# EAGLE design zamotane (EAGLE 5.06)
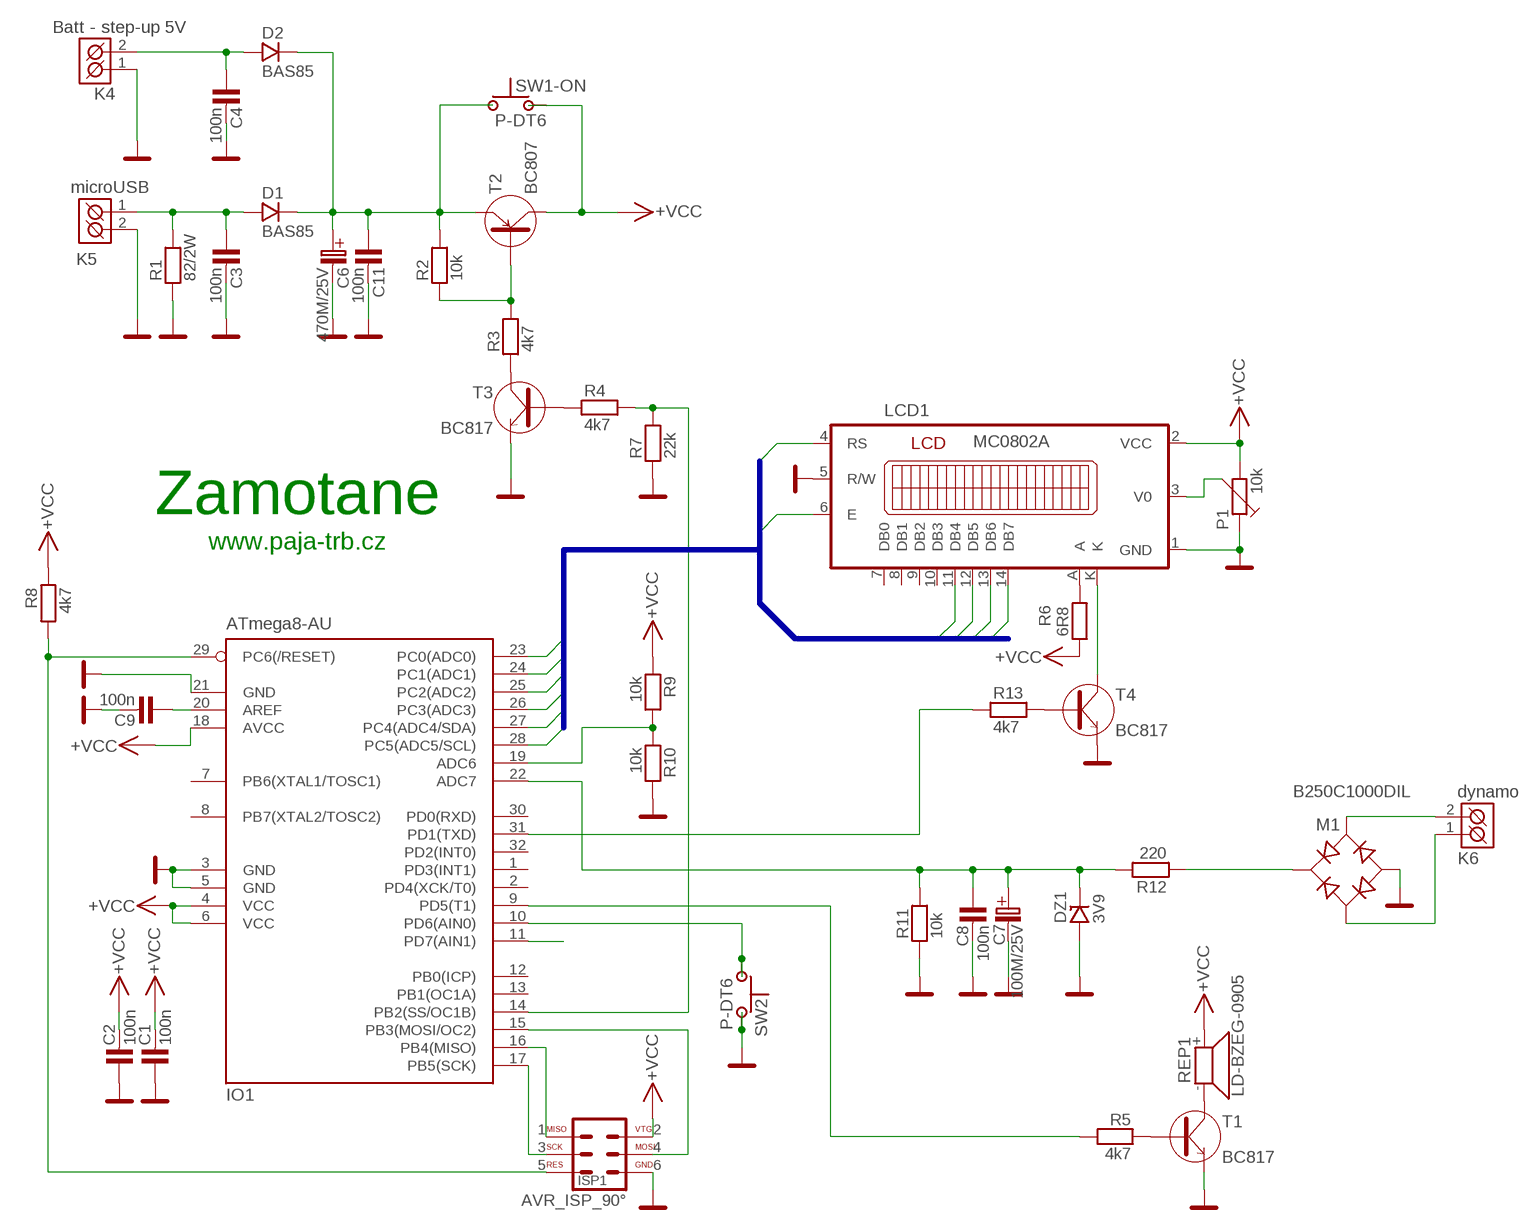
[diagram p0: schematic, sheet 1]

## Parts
C1  100n  C-KER_0805  [0805]
C2  100n  C-KER_0805  [0805]
C3  100n  C-KERAMIK_SMD_1206  [1206]
C4  100n  C-KERAMIK_SMD_1206  [1206]
C6  470M/25V  C-EL_5  [C-EL_5]
C7  100M/25V  [C_EL_2,5]
C8  100n  C-KERAMIK_SMD_1206  [1206]
C9  100n  C-KER_0805  [0805]
C11  100n  C-KERAMIK_SMD_1206  [1206]
D1  BAS85  1N4148.  [SOD-80]
D2  BAS85  1N4148.  [SOD-80]
DZ1  3V9  D-BZV55C_SMD_0,5W-ZENER  [SOD-80]
IO1  ATmega8-AU  MEGA8-AI  [TQFP32-08]
ISP1  AVR_ISP_90°  [MLW06A]
K4  Batt - step-up 5V  ARK500/2  [ARK500/2]
K5  microUSB  ARK500/2  [ARK500/2]
K6  dynamo  ARK500/2  [ARK500/2]
LCD1  MC0802A  [MC0802A-SYL]
M1  B250C1000DIL  D-B250C1000DIL_MUSTEK  [DM_DB1]
P1  10k  TRIMRPT6H  [PT6H]
R1  82/2W  R__2W  [R-_2W]
R2  10k  R_1206  [1206]
R3  4k7  R_1206  [1206]
R4  4k7  R_1206  [1206]
R5  4k7  R_1206  [1206]
R6  6R8  R_1206  [1206]
R7  22k  R_1206  [1206]
R8  4k7  R_1206  [1206]
R9  10k  R_0805  [0805]
R10  10k  R_0805  [0805]
R11  10k  R_1206  [1206]
R12  220  R_1206  [1206]
R13  4k7  R_1206  [1206]
REP1  LD-BZEG-0905  SIR_0905  [LD-BZEG-0905]
SW1-ON  P-DT6  [P-DT6]
SW2  P-DT6  [P-DT6]
T1  BC817  [SOT-23]
T2  BC807  [SOT-23]
T3  BC817  [SOT-23]
T4  BC817  BC846  [SOT-23]

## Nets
+5V: C6.C+(C_EL+) C11.1 D1.K D2.K R2.2 SW1-ON.1 SW1-ON.1A T2.2(E)
ADC7: C7.C+(C_EL+) C8.1 DZ1.K IO1.22(ADC7) R11.2 R12.2
DB4: IO1.25(PC2(ADC2)) LCD1.11(DB4)
DB5: IO1.26(PC3(ADC3)) LCD1.12(DB5)
DB6: IO1.27(PC4(ADC4/SDA)) LCD1.13(DB6)
DB7: IO1.28(PC5(ADC5/SCL)) LCD1.14(DB7)
E: IO1.24(PC1(ADC1)) LCD1.4(RS)
GND: C1.1 C2.1 C3.2 C4.2 C6.C-(C_EL-) C7.C-(C_EL-) C8.2 C9.2 C11.2 DZ1.A IO1.3(GND) IO1.5(GND) IO1.21(GND) ISP1.6 K4.1(K1) K5.2(K2) LCD1.1(GND) LCD1.5(R/W) M1.- P1.1 R1.1 R7.1 R10.2 R11.1 SW2.2 SW2.2A T1.2(E) T3.2(E) T4.2(E)
N$1: IO1.16(PB4(MISO)) ISP1.1
N$2: C9.1 IO1.20(AREF)
N$3: K6.1(K1) M1.AC2
N$4: R5.1 T1.1(B)
N$5: IO1.9(PD5(T1)) R5.2
N$6: LCD1.K T4.3(C)
N$7: K6.2(K2) M1.AC1
N$8: IO1.19(ADC6) R9.2 R10.1
N$9: IO1.17(PB5(SCK)) ISP1.3
N$10: LCD1.A R6.1
N$11: IO1.15(PB3(MOSI/OC2)) ISP1.4
N$12: REP1.- T1.3(C)
N$13: M1.+ R12.1
N$14: LCD1.3(V0) P1.3
N$15: C3.1 D1.A K5.1(K1) R1.2
N$16: C4.1 D2.A K4.2(K2)
N$17: R3.1 T3.3(C)
N$19: IO1.10(PD6(AIN0)) SW2.1 SW2.1A
N$21: R4.1 T3.1(B)
N$22: R2.1 R3.2 T2.1(B)
N$23: IO1.14(PB2(SS/OC1B)) R4.2 R7.2
N$28: R13.2 T4.1(B)
PD1: IO1.31(PD1(TXD)) R13.1
PD7: IO1.11(PD7(AIN1))
RESET: IO1.29(PC6(/RESET)) ISP1.5 R8.2
RS: IO1.23(PC0(ADC0)) LCD1.6(E)
VCC: C1.2 C2.2 IO1.4(VCC) IO1.6(VCC) IO1.18(AVCC) ISP1.2 LCD1.2(VCC) P1.2 R6.2 R8.1 R9.1 REP1.+ SW1-ON.2 SW1-ON.2A T2.3(C) ; supply symbol labelled +VCC
Unconnected: IO1.1(PD3(INT1)) IO1.2(PD4(XCK/T0)) IO1.7(PB6(XTAL1/TOSC1)) IO1.8(PB7(XTAL2/TOSC2)) IO1.12(PB0(ICP)) IO1.13(PB1(OC1A)) IO1.30(PD0(RXD)) IO1.32(PD2(INT0)) LCD1.7(DB0) LCD1.8(DB1) LCD1.9(DB2) LCD1.10(DB3)

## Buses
DB4,DB5,DB6,DB7,E,RS

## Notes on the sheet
- Zamotane
- www.paja-trb.cz

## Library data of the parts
C1 C2 C9 = #PaJa_32:C-KER: Kondenzator - keramicky
C3 C4 C8 C11 = #PaJa_31:C-KERAMIK: Kondenzator - keramicky
C6 = #PaJa_32:C-EL: Kondenzator - elektrolyticky
C7 = #PaJa_C-el_2:100M/25V
D1 D2 = #PaJa_32:1N4148: Univerzalni dioda - 0,15A, 75V
DZ1 = #PaJa_32:D-?-ZENER: Zenerova dioda
IO1 = atmel:MEGA8: MICROCONTROLLER 8 Kbytes FLASH, 1 kbytes SRAM, 512 bytes EEPROM, USART, 6-channel 10 bit ADC, 2-channel 8 bit ADC Pin compatible with Atmega48, ATMega88, ATMega168 Source: avr.lbr
ISP1 = #PaJa_32:AVR_ISP: AVR ISP konektor (dle standardu)
K4-K6 = #PaJa_konektory:ARK500/2: Svorkovnice - roztec 5mm - dvojita
LCD1 = #PaJa_displeje:?0802A: LCD - 2x8 + LED
M1 = #PaJa_32:D-?_MUSTEK: Diodovy mustek - Graetz
P1 = #PaJa_32:TRIMR: Trimr
R1-R13 = #PaJa_32:R: Rezistor
REP1 = #PaJa_32:SIR: Piezo-sirenka - 70dB - 3V az 16V
SW1-ON SW2 = #PaJa_prepinace:P-DT: Tlacitkovy spinac
T1 T3 = #PaJa_32:BC817: SMD tranzistor - NPN - ekv. BC337
T2 = #PaJa_32:BC807: SMD tranzistor - PNP - ekv. BC327
T4 = #PaJa_32:BC846: SMD tranzistor - NPN - ekv. BC546

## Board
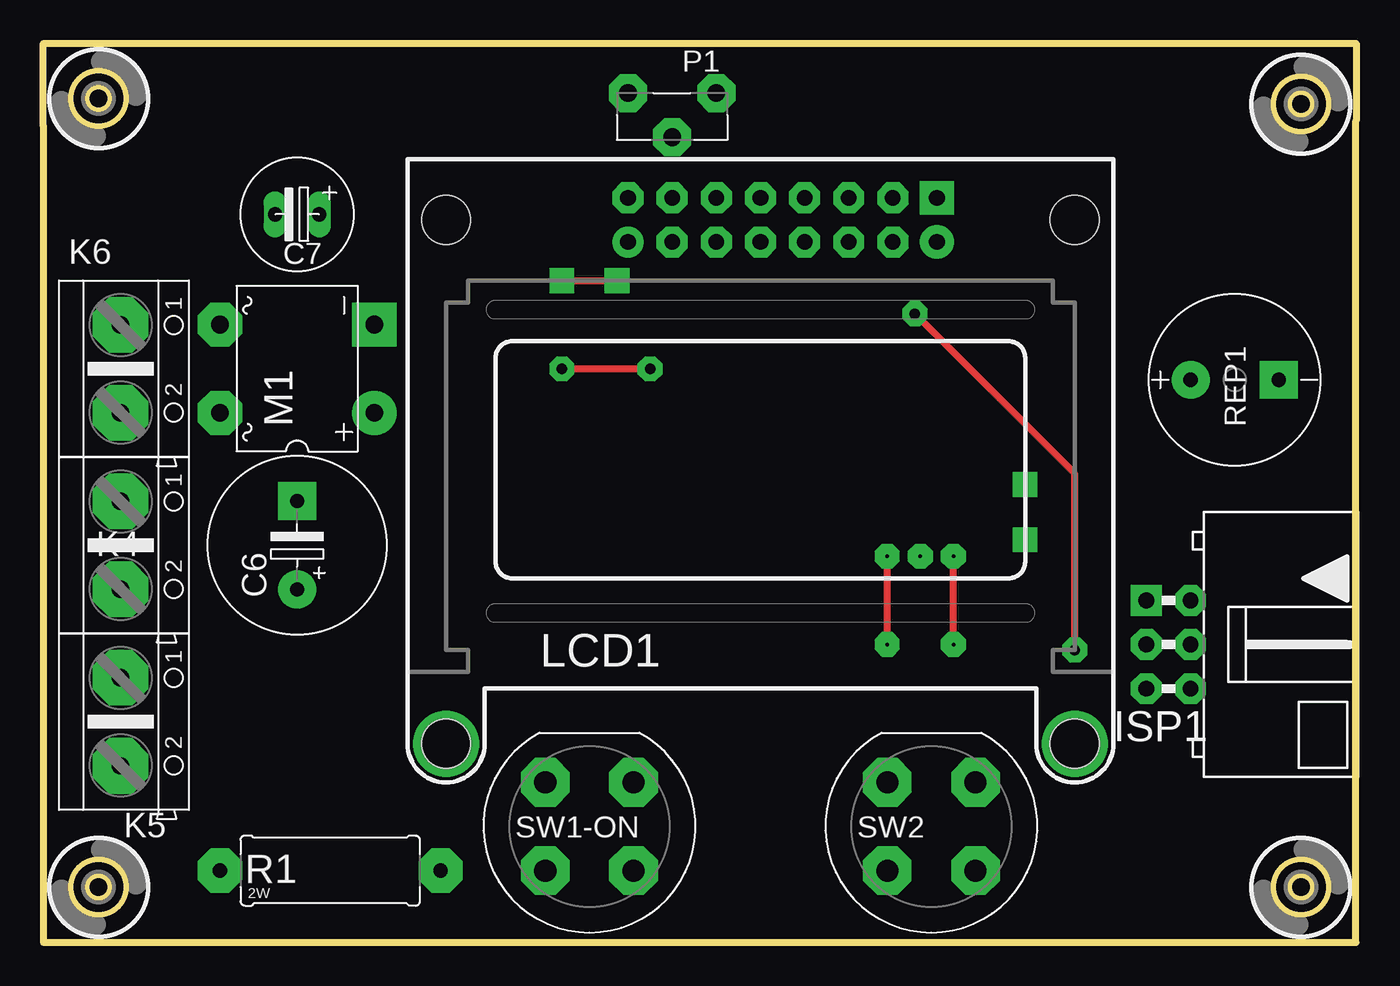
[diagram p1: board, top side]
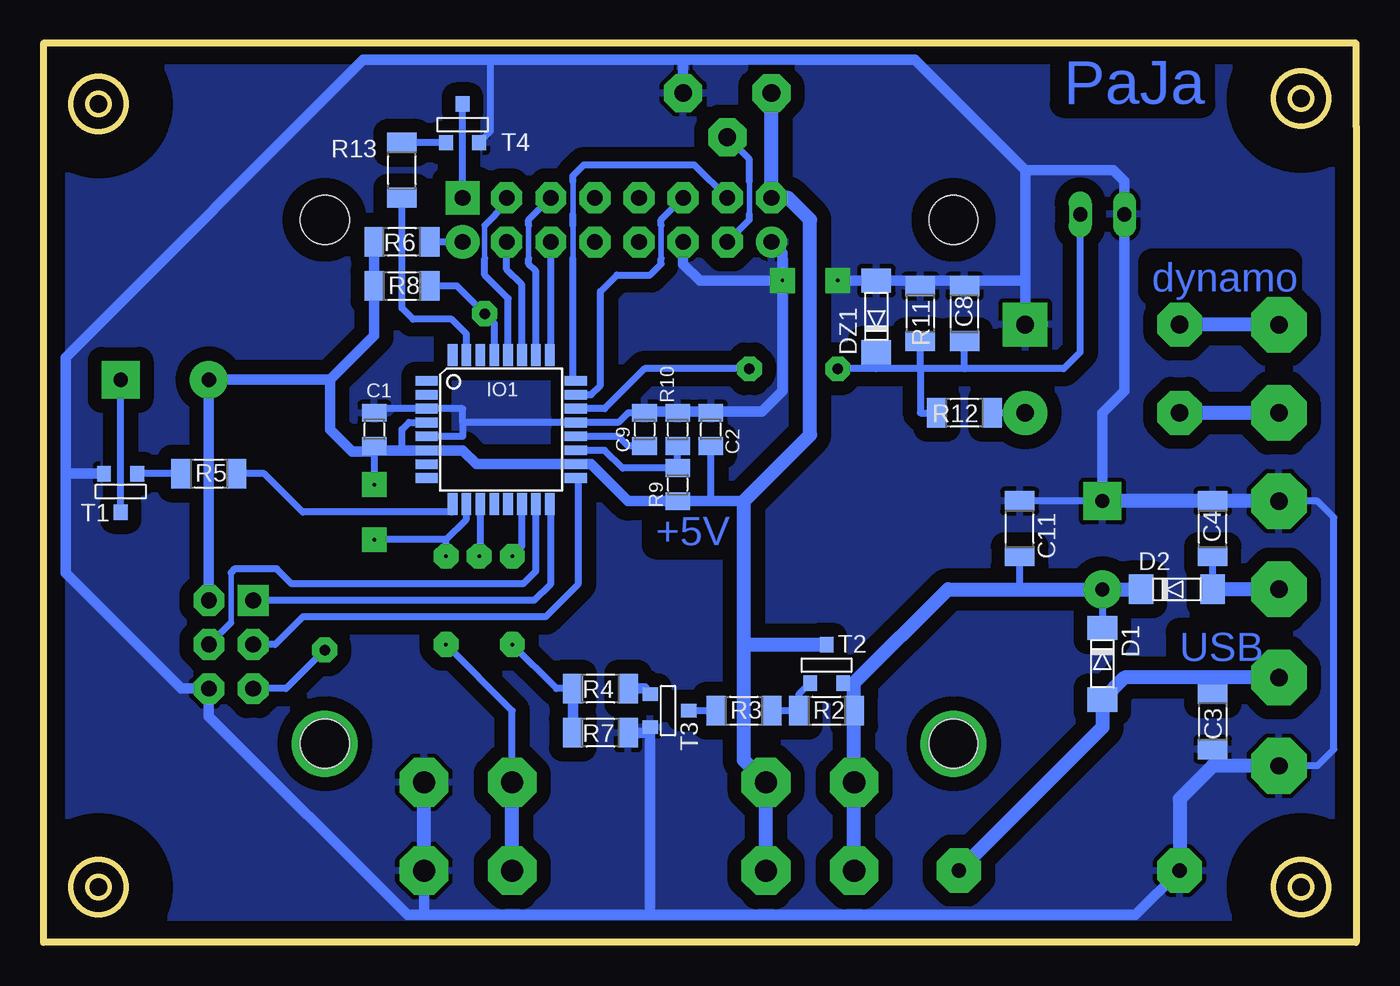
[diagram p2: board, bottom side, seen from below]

Size 75.56 x 51.75 mm. Coordinates in mm from the lower left corner, seen from the top.
Outline: 75.55,47.3 75.55,0 0,0 0,46.98
Outline: 0,46.99 0,51.75 75.56,51.75 75.56,47.31
Copper layers (1*16): Top 0.035mm / dielectric 1.5mm / Bottom 0.035mm
Design rules "default": minimum track width 10mil, minimum drill 24mil, track to track 8mil, track to pad 8mil, pad to pad 8mil, via to via 8mil, smd to smd 8mil, copper to edge 40mil, drill to drill 8mil, minimum pad ring 10mil, minimum via ring 8mil, stop-mask expansion 4mil, vias tented up to drill 0mil, thermal gap 10mil

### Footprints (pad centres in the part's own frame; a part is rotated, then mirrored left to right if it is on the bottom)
0805 = smd 1.016 x 1.422: 1 -0.953,0; 2 0.953,0
1206 = smd 1.143 x 1.702: 1 -1.587,0; 2 1.587,0
C-EL_5 = drill 0.813 pad 2.184 round: C+ -2.54,0 | drill 0.813 pad 2.184 square: C- 2.54,0
C_EL_2,5 = drill 0.813 pad 1.27 long: C+ -1.27,0; C- 1.27,0
SOD-80 = smd 1.397 x 1.702: A 1.905,0; K -2.223,0
TQFP32-08 = smd 1.27 x 0.559: 1 -4.293,2.8; 2 -4.293,2; 3 -4.293,1.2; 4 -4.293,0.4; 5 -4.293,-0.4; 6 -4.293,-1.2; 7 -4.293,-2; 8 -4.293,-2.8; 17 4.293,-2.8; 18 4.293,-2; 19 4.293,-1.2; 20 4.293,-0.4; 21 4.293,0.4; 22 4.293,1.2; 23 4.293,2; 24 4.293,2.8 | smd 0.559 x 1.27: 9 -2.8,-4.293; 10 -2,-4.293; 11 -1.2,-4.293; 12 -0.4,-4.293; 13 0.4,-4.293; 14 1.2,-4.293; 15 2,-4.293; 16 2.8,-4.293; 25 2.8,4.293; 26 2,4.293; 27 1.2,4.293; 28 0.4,4.293; 29 -0.4,4.293; 30 -1.2,4.293; 31 -2,4.293; 32 -2.8,4.293
MLW06A = drill 0.914 pad 1.778 square: 1 -2.54,-1.27 | drill 0.914 pad 1.778 octagon: 2 -2.54,1.27; 3 0,-1.27; 4 0,1.27; 5 2.54,-1.27; 6 2.54,1.27
ARK500/2 = drill 1 pad 3.2 octagon: 1 -2.54,0; 2 2.54,0
MC0802A-SYL = drill 0.9 pad 1.778 round: 1 -7.62,12.7 | drill 0.9 pad 1.778 octagon: 2 -7.62,15.24; 3 -5.08,12.7; 4 -5.08,15.24; 5 -2.54,12.7; 6 -2.54,15.24; 7 0,12.7; 8 0,15.24; 9 2.54,12.7; 10 2.54,15.24; 11 5.08,12.7; 12 5.08,15.24; 13 7.62,12.7; 14 7.62,15.24 | drill 0.9 pad 1.93 round: A 10.16,12.7 | drill 0.9 pad 1.93 square: K 10.16,15.24 | hole 2.8: -18.098,-16.192; 18.098,-16.192; 18.098,13.97; -18.098,13.97
DM_DB1 = drill 1.016 pad 2.54 round: + -2.54,-4.445 | drill 1.016 pad 2.54 square: - 2.54,-4.445 | drill 1.016 pad 2.54 octagon: AC1 -2.54,4.445; AC2 2.54,4.445
PT6H = drill 1.016 pad 2.184 octagon: 1 -2.54,-1.27; 2 2.54,-1.27; 3 0,1.27
R-_2W = drill 0.813 pad 2.54 octagon: 1 -6.35,0; 2 6.35,0
LD-BZEG-0905 = drill 0.813 pad 2.184 round: + -2.54,0 | drill 0.813 pad 2.184 square: - 2.54,0
P-DT6 = drill 1.27 pad 2.8 octagon: 1 -2.54,-2.54; 1A -2.54,2.54; 2 2.54,-2.54; 2A 2.54,2.54
SOT-23 = smd 0.787 x 0.889: 1 -0.953,-0.953; 2 0.953,-0.953; 3 0,1.27
HOLE_3,0 = hole 3.2: 0,0

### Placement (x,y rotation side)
C1  56.52,29.53 270 bottom
C2  37.15,29.53 270 bottom
C3  8.26,12.7 270 bottom
C4  8.26,23.81 90 bottom
C6  14.61,22.86 90 top
C7  14.61,41.91 180 top
C8  22.54,36.2 90 bottom
C9  40.96,29.53 90 bottom
C11  19.37,23.81 90 bottom
D1  14.61,15.88 270 bottom
D2  10.16,20.32 0 bottom
DZ1  27.62,36.2 90 bottom
IO1  49.21,29.53 0 bottom
ISP1  64.77,17.14 270 top
K4  4.45,22.86 270 top
K5  4.45,12.7 270 top
K6  4.45,33.02 270 top
LCD1  41.27,27.62 0 top
M1  14.61,33.02 90 top
P1  36.2,47.62 180 top
R1  16.51,4.13 0 top
R2  30.48,13.34 0 bottom
R3  35.24,13.34 0 bottom
R4  43.5,14.61 180 bottom
R5  66.04,26.99 0 bottom
R6  54.93,40.32 180 bottom
R7  43.5,12.06 180 bottom
R8  54.93,37.78 0 bottom
R9  39.05,26.35 90 bottom
R10  39.05,29.53 90 bottom
R11  25.08,36.2 270 bottom
R12  22.54,30.48 180 bottom
R13  54.93,44.45 90 bottom
REP1  68.58,32.38 0 top
SW1-ON  31.43,6.67 0 top
SW2  51.12,6.67 0 top
T1  71.12,26.04 180 bottom
T2  30.48,15.88 0 bottom
T3  39.69,13.34 270 bottom
T4  51.44,46.99 0 bottom
U$1  [HOLE_3,0]  3.17,3.17 0 top
U$2  [HOLE_3,0]  72.39,48.26 0 top
U$3  [HOLE_3,0]  72.39,3.17 0 top
U$4  [HOLE_3,0]  3.17,48.58 0 top

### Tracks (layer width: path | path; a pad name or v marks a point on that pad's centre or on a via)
+5V
  Bottom 0.406: 19.37,20.32 C11.1 | 28.89,14.92 T2.2 | C6.C+ D1.K
  Bottom 0.813: SW1-ON.1 SW1-ON.1A R2.2 28.89,14.92 23.5,20.32 19.37,20.32 C6.C+ D2.K
ADC7  (via drill 0.6 pad 1.42)
  Top 0.406: v29.84,33.02 v34.92,33.02
  Bottom 0.406: v34.92,33.02 40.96,33.02 43.25,30.73 IO1.22 | R12.2 25.08,30.48 25.08,33.02 | 22.54,33.02 16.83,33.02 15.88,33.97 C7.C+ | 22.54,33.02 25.08,33.02 | 25.08,33.02 27.62,33.02 | 27.62,33.02 v29.84,33.02 | 27.62,33.02 DZ1.K | 25.08,33.02 R11.2 | 22.54,33.02 C8.1
DB4
  Bottom 0.406: LCD1.11 46.35,33.88 IO1.25
DB5
  Bottom 0.305: 47.62,39.37 47.62,41.27
  Bottom 0.406: LCD1.12 47.62,41.59 47.62,41.27 | 47.62,39.37 47.62,39.05 47.21,38.64 IO1.26
DB6
  Bottom 0.406: LCD1.13 48.9,38.73 48.01,37.85 IO1.27
DB7
  Bottom 0.305: 50.16,39.37 50.16,41.27
  Bottom 0.406: LCD1.14 48.9,42.55 50.16,41.27 | 50.16,39.37 50.16,38.42 48.81,37.06 IO1.28
E
  Bottom 0.305: 45.09,41.91 45.09,43.81 | 45.09,39.37 45.09,41.27
  Bottom 0.406: LCD1.4 38.1,44.77 44.45,44.77 45.09,44.13 45.09,43.81 | 44.51,32.33 IO1.24 45.09,32.49 45.09,39.37 | 45.09,41.27 45.09,41.91
GND  (via drill 0.2 pad 1.42)
  Top 0.406: v29.84,38.1 v33.02,38.1
  Bottom 0.406: IO1.5 51.44,29.13 51.44,29.93 | 51.44,29.93 51.44,30.73 IO1.3 56.27,30.73 C1.1 56.52,30.8 | 51.44,29.93 IO1.21 42.46,29.93 41.91,30.48 C9.2 40.96,30.56 | 38.73,30.56 C2.1 | C4.2 K4.1 2.22,25.4 1.27,24.45 1.27,11.11 2.22,10.16 K5.2 | C6.C- C11.2 | T3.2 40.64,12.06 | SW2.2A | T4.2 49.85,46.67 49.85,50.8 | 39.05,30.56 R10.2 | 8.26,10.16 C3.2 | 22.54,38.1 C8.2 | 25.4,38.1 R11.1
  Bottom 0.61: 40.96,30.56 39.05,30.56 38.73,30.56 34.21,30.56 33.02,31.75 v33.02,38.1 | C6.C- 14.61,30.48 13.34,31.75 C7.C- 13.34,43.81 13.97,44.45 19.05,44.45 | 19.05,44.45 19.05,38.1 | 19.05,38.1 M1.- | 40.64,12.06 R7.1 | 40.64,1.59 53.66,1.59 | 53.66,1.59 SW2.2 | 53.66,1.59 54.61,1.59 66.04,13.02 ISP1.6 67.63,14.61 74.3,21.27 74.3,26.99 | 40.64,1.59 T3.2 | 74.3,26.99 74.3,33.66 57.15,50.8 49.85,50.8 38.73,50.8 | 74.3,26.99 T1.2 | LCD1.5 38.73,39.05 37.78,38.1 v33.02,38.1 | 19.05,38.1 22.54,38.1 25.4,38.1 DZ1.A 28.89,38.1 v29.84,38.1 | LCD1.1 33.02,39.69 v33.02,38.1 | 19.05,44.45 25.4,50.8 38.73,50.8 | 38.73,50.8 P1.1 | 40.64,1.59 12.7,1.59 R1.1
  Bottom 0.813: SW2.2 SW2.2A | C6.C- C4.2 K4.1 | K5.2 8.26,10.16 10.16,8.26 R1.1
  pour Bottom (isolate 0.813): 0,51.75 0,0 75.56,0 75.56,51.75 0.32,51.75
N$1
  Bottom 0.406: 46.35,25.18 arc-90 IO1.16 arc90 46.35,25.18 | 46.35,25.18 46.35,20.64 47.31,19.68 ISP1.1
N$2
  Bottom 0.406: C9.1 41.91,28.57 42.46,29.13 IO1.20
N$3
  Bottom 0.813: K6.1 M1.AC2
N$4
  Bottom 0.406: R5.1 T1.1
N$5
  Bottom 0.406: IO1.9 52.07,25.18 52.07,24.77 60.64,24.77 62.87,26.99 R5.2
N$6
  Bottom 0.406: LCD1.K T4.3
N$7
  Bottom 0.813: K6.2 M1.AC1
N$8
  Bottom 0.406: IO1.19 43.25,28.33 42.23,27.3 R9.2 R10.1
N$9
  Bottom 0.406: IO1.17 44.77,26.57 44.77,20.64 46.67,18.73 60.64,18.73 62.23,17.14 ISP1.3
N$10
  Bottom 0.406: LCD1.A R6.1
N$11
  Bottom 0.305: 64.77,21.27 64.77,18.41
  Bottom 0.406: 64.77,18.41 ISP1.4 | 64.77,21.27 64.55,21.5 62.13,21.5 61.28,20.64 47.94,20.64 47.21,21.37 IO1.15
N$12
  Bottom 0.406: T1.3 REP1.-
N$13
  Bottom 0.406: M1.+ R12.1
N$14
  Bottom 0.305: 34.92,41.91 34.92,43.81
  Bottom 0.406: P1.3 34.92,45.09 34.92,43.81 | LCD1.3 34.92,41.59 34.92,41.91
N$15
  Bottom 0.406: 8.26,15.24 C3.1
  Bottom 0.813: K5.1 8.26,15.24 13.34,15.24 D1.A 14.61,12.38 R1.2
N$16
  Bottom 0.406: D2.A C4.1
  Bottom 0.813: K4.2 D2.A
N$17
  Bottom 0.406: R3.1 T3.3
N$19  (via drill 0.2 pad 1.42)
  Top 0.406: v52.39,17.14 v52.39,22.23
  Bottom 0.406: SW2.1A 48.58,13.34 v52.39,17.14 | 52.39,23.18 v56.52,23.18 | IO1.10 51.21,24.35 52.39,23.18 | v52.39,22.23 52.39,23.18
  Bottom 0.813: SW2.1 SW2.1A
N$21
  Bottom 0.406: 40.96,14.61 T3.1
  Bottom 0.61: R4.1 40.96,14.61
N$22
  Bottom 0.406: T2.1 32.07,14.29 R2.1 R3.2
N$23  (via drill 0.2 pad 1.42)
  Top 0.406: v48.58,17.14 v48.58,22.23
  Bottom 0.406: R4.2 46.04,14.61 v48.58,17.14 | IO1.14 48.01,22.79 v48.58,22.23
  Bottom 0.61: R7.2 R4.2
N$28
  Bottom 0.406: T4.1 R13.2
N$31  (via drill 0.8 pad 3.81)
  other vias: 59.37,11.43
N$32  (via drill 0.8 pad 3.81)
  other vias: 23.18,11.43
PD1
  Bottom 0.406: IO1.31 51.21,35.02 52.07,35.88 54.29,35.88 54.93,36.51 R13.1
PD7  (via drill 0.2 pad 1.42)
  Bottom 0.406: IO1.11 50.41,22.61 v50.48,22.23
RESET  (via drill 0.6 pad 1.42)
  Top 0.406: v59.37,16.83 59.37,26.99 v50.16,36.2
  Bottom 0.406: IO1.29 49.61,35.64 v50.16,36.2 51.75,37.78 R8.2 | v59.37,16.83 61.59,14.61 ISP1.5
RS
  Bottom 0.305: 40.01,39.37 40.01,41.27
  Bottom 0.406: LCD1.6 40.01,41.59 40.01,41.27 | IO1.23 44.04,31.53 43.5,32.07 43.5,37.47 42.55,38.42 40.64,38.42 40.01,39.05 40.01,39.37
VCC  (via drill 0.2 pad 1.42)
  Bottom 0.406: IO1.4 54.53,29.93 54.93,29.53 54.93,28.33 | 56.52,28.26 56.45,28.33 56.27,28.33 C1.2 v56.52,26.35 | 37.15,25.4 C2.2
  Bottom 0.61: R6.2 R8.1 56.52,34.92 59.05,32.38 | ISP1.2 REP1.+ 59.05,32.38 | 56.27,28.33 54.93,28.33 IO1.6 51.44,28.33 50.63,27.53 IO1.18 44.04,27.53 41.91,25.4 R9.1 37.15,25.4 35.24,25.4 | 56.52,28.26 57.78,28.26 59.05,29.53 59.05,32.38
  Bottom 0.813: P1.2 LCD1.2 32.7,42.86 31.43,41.59 31.43,29.21 35.24,25.4 35.24,17.14 | SW1-ON.2 SW1-ON.2A 35.24,10.48 35.24,17.14 | 35.24,17.14 T2.3
(copper drawn outside any net)
  shapes: Bottom circle x4

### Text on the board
Bottom: PaJa | dynamo | +5V | USB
